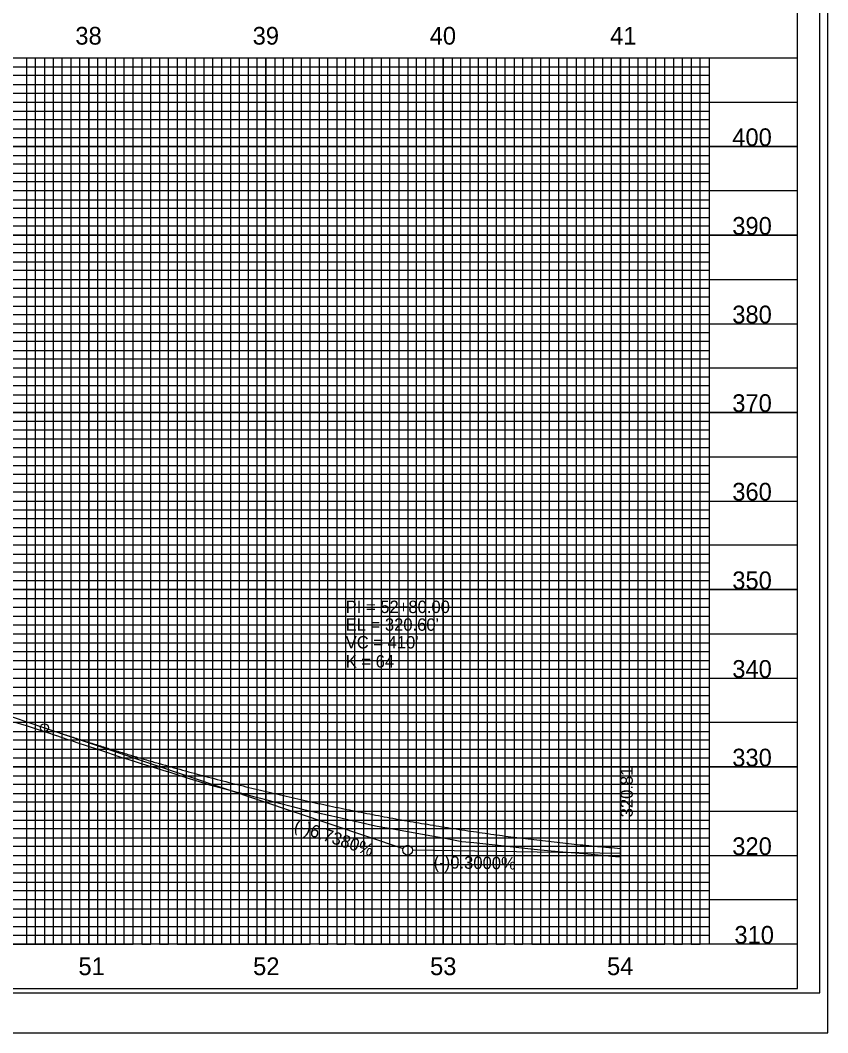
# Model space of a CAD drawing. Extents: x 571503 to 593215, y -77195 to -51828.
# Drawn here: x 583558 to 584014, y -74015 to -73444 of the extents above; entities that cross this region are included whole.
import ezdxf

# ---------------------------------------------------------------- set-up
doc = ezdxf.new("R2010")
doc.units = 0
for name, color, linetype in [('Exist Vertical Profile Ground Line', 7, 'Continuous'), ('Exist Vertical Profile Horizontal Axis Label Major', 7, 'Continuous'), ('Exist Vertical Profile Vertical Axis Label', 7, 'Continuous'), ('Prop Vertical Profile Curve Label', 7, 'Continuous'), ('Prop Vertical Profile Grade', 7, 'Continuous'), ('Prop Vertical Profile Grade Label', 7, 'Continuous'), ('Prop VPI Label', 7, 'Continuous'), ('Sheet Cutting Line CELL', 7, 'Continuous'), ('Sheet DOT Grid CELL', 7, 'Continuous'), ('Sheet Layout Profile Border Port 2', 7, 'Continuous'), ('Sheet Plot Border Inside CELL', 7, 'Continuous'), ('Sheet Plot Border Outside CELL', 7, 'Continuous'), ('Sheet Profile CELL', 7, 'Continuous'), ('Sheet Profile Grid Major CELL', 7, 'Continuous'), ('Sheet Profile Grid Middle CELL', 7, 'Continuous'), ('Sheet Profile Grid Minor CELL', 7, 'Continuous')]:
    doc.layers.add(name, color=color, linetype=linetype)

msp = doc.modelspace()

# ---------------------------------------------------------------- linework, layer by layer
at = {"layer": 'Exist Vertical Profile Ground Line'}
for points in [[(583555.87, -73840.05), (583558.44, -73840.84), (583561.62, -73841.79), (583562.84, -73842.15), (583567.37, -73843.66), (583573.12, -73845.57), (583578.65, -73847.4), (583578.87, -73847.47)], [(583578.87, -73847.47), (583584.62, -73849.4), (583587.3, -73850.29), (583590.38, -73851.31), (583596.13, -73853.22), (583601.88, -73855.13), (583607.63, -73857.04), (583610.72, -73858.07), (583613.38, -73858.96), (583615.62, -73859.71), (583619.13, -73860.81), (583624.88, -73862.62), (583630.63, -73864.43), (583632.26, -73864.94), (583636.38, -73866.19), (583640.7, -73867.49), (583642.14, -73867.94), (583647.89, -73869.75), (583653.64, -73871.56), (583659.39, -73873.37), (583663.93, -73874.8), (583665.14, -73875.16), (583668.66, -73876.22), (583670.89, -73876.81), (583676.64, -73878.31), (583680.58, -73879.33), (583682.39, -73879.8), (583688.15, -73881.28), (583690.06, -73881.77), (583693.9, -73882.77), (583699.65, -73884.26), (583705.4, -73885.76), (583711.15, -73887.26), (583712.06, -73887.5), (583716.9, -73888.74), (583717.61, -73888.92), (583719.13, -73889.27), (583722.65, -73890.06), (583728.12, -73891.3), (583728.4, -73891.37), (583734.15, -73892.68), (583739.26, -73893.84), (583739.91, -73893.99), (583745.66, -73895.29), (583751.41, -73896.59), (583757.16, -73897.9), (583759.8, -73898.5), (583762.91, -73899.06), (583766.56, -73899.72), (583768.66, -73900.1), (583785.35, -73903.1), (583799, -73905.58), (583807.46, -73907.1), (583814.21, -73907.83), (583831.48, -73909.69), (583846.42, -73911.31), (583855.79, -73912.32), (583862.22, -73912.89), (583878.67, -73914.22), (583894.28, -73915.59), (583896.98, -73915.81)]]:
    msp.add_lwpolyline(points, dxfattribs=at)
at = {"layer": 'Prop Vertical Profile Curve Label'}
msp.add_circle((583571.98, -73843.03), 2.25, dxfattribs=at)
at = {"layer": 'Prop Vertical Profile Grade'}
msp.add_line((583441.98, -73799.23), (583571.98, -73843.03), dxfattribs=at)
msp.add_spline([(583571.98, -73843.03), (583578.48, -73845.2), (583584.98, -73847.34), (583591.48, -73849.45), (583597.98, -73851.52), (583604.48, -73853.56), (583610.98, -73855.57), (583617.48, -73857.55), (583623.98, -73859.49), (583630.48, -73861.4), (583636.98, -73863.27), (583643.48, -73865.11), (583649.98, -73866.92), (583656.48, -73868.7), (583662.98, -73870.44), (583669.48, -73872.15), (583675.98, -73873.82), (583682.48, -73875.46), (583688.98, -73877.07), (583695.48, -73878.65), (583701.98, -73880.19), (583708.48, -73881.7), (583714.98, -73883.18), (583721.48, -73884.62), (583727.98, -73886.03), (583734.48, -73887.41), (583740.98, -73888.75), (583747.48, -73890.06), (583753.98, -73891.34), (583760.48, -73892.59), (583766.98, -73893.8), (583773.48, -73894.98), (583779.98, -73896.12), (583786.48, -73897.23), (583792.98, -73898.31), (583799.48, -73899.36), (583805.98, -73900.37), (583812.48, -73901.35), (583818.98, -73902.29), (583825.48, -73903.21), (583831.98, -73904.09), (583838.48, -73904.93), (583844.98, -73905.75), (583851.48, -73906.53), (583857.98, -73907.27), (583864.48, -73907.99), (583870.98, -73908.67), (583877.48, -73909.32), (583883.98, -73909.93), (583890.48, -73910.51), (583896.98, -73911.06)], degree=3, dxfattribs=at)
at = {"layer": 'Prop VPI Label'}
for p, q in [((583571.98, -73843.03), (583774.38, -73911.22)), ((583896.98, -73913.89), (583779.73, -73912.14))]:
    msp.add_line(p, q, dxfattribs=at)
msp.add_circle((583776.98, -73912.09), 2.75, dxfattribs=at)
at = {"layer": 'Sheet Cutting Line CELL'}
msp.add_line((582329.98, -74015.09), (584013.98, -74015.09), dxfattribs=at)
at = {"layer": 'Sheet DOT Grid CELL'}
for p, q in [((582496.98, -73465.09), (583996.87, -73465.09)), ((583596.98, -73465.09), (583596.98, -73965.09)), ((583646.98, -73465.09), (583646.98, -73965.09)), ((583696.98, -73465.09), (583696.98, -73965.09)), ((583746.98, -73465.09), (583746.98, -73965.09)), ((583796.98, -73465.09), (583796.98, -73965.09)), ((583846.98, -73465.09), (583846.98, -73965.09)), ((583896.98, -73465.09), (583896.98, -73965.09)), ((583946.98, -73465.09), (583946.98, -73965.09)), ((582496.98, -73515.09), (583996.87, -73515.09)), ((582496.98, -73565.09), (583996.87, -73565.09)), ((582496.98, -73615.09), (583996.87, -73615.09)), ((582496.98, -73665.09), (583996.87, -73665.09)), ((582496.98, -73715.09), (583996.87, -73715.09)), ((582496.98, -73765.09), (583996.87, -73765.09)), ((582496.98, -73815.09), (583996.87, -73815.09)), ((582496.98, -73865.09), (583996.87, -73865.09)), ((582496.98, -73915.09), (583996.87, -73915.09))]:
    msp.add_line(p, q, dxfattribs=at)
at = {"layer": 'Sheet Layout Profile Border Port 2'}
msp.add_lwpolyline([(582546.98, -73465.09), (583946.98, -73465.09), (583946.98, -73965.09), (582546.98, -73965.09)], close=True, dxfattribs=at)
at = {"layer": 'Sheet Plot Border Inside CELL'}
msp.add_lwpolyline([(582342.98, -73992.64), (584009.48, -73992.64), (584009.48, -72937.54), (582342.98, -72937.54)], close=True, dxfattribs=at)
at = {"layer": 'Sheet Plot Border Outside CELL'}
msp.add_lwpolyline([(582329.98, -74015.09), (584013.98, -74015.09), (584013.98, -72915.09), (582329.98, -72915.09)], close=True, dxfattribs=at)
at = {"layer": 'Sheet Profile CELL'}
for p, q in [((582496.98, -73465.09), (583996.98, -73465.09)), ((583996.98, -73965.09), (582496.98, -73965.09)), ((582496.98, -73990.09), (583996.98, -73990.09))]:
    msp.add_line(p, q, dxfattribs=at)
msp.add_lwpolyline([(583996.98, -72940.09), (582496.98, -72940.09), (582496.98, -73990.09), (583996.98, -73990.09)], close=True, dxfattribs=at)
at = {"layer": 'Sheet Profile Grid Major CELL'}
for p, q in [((583596.98, -73465.09), (583646.98, -73465.09)), ((583696.98, -73465.09), (583746.98, -73465.09)), ((583796.98, -73465.09), (583846.98, -73465.09)), ((583896.98, -73465.09), (583946.98, -73465.09)), ((583896.98, -73965.09), (583896.98, -73965.09))]:
    msp.add_line(p, q, dxfattribs=at)
for points in [[(583546.98, -73965.09), (583596.98, -73965.09), (583596.98, -73465.09), (583646.98, -73465.09), (583646.98, -73965.09), (583696.98, -73965.09), (583696.98, -73465.09), (583746.98, -73465.09), (583746.98, -73965.09), (583796.98, -73965.09), (583796.98, -73465.09), (583846.98, -73465.09), (583846.98, -73965.09), (583896.98, -73965.09), (583896.98, -73965.09), (583896.98, -73465.09), (583946.98, -73465.09), (583946.98, -73965.09)], [(583996.98, -73515.09), (582496.98, -73515.09)], [(583996.98, -73565.09), (582496.98, -73565.09), (582496.98, -73615.09), (583996.98, -73615.09)], [(583996.98, -73665.09), (582496.98, -73665.09), (582496.98, -73715.09), (583996.98, -73715.09)], [(583996.98, -73765.09), (582496.98, -73765.09), (582496.98, -73815.09), (583996.98, -73815.09)], [(583996.98, -73865.09), (582496.98, -73865.09), (582496.98, -73865.09), (582496.98, -73915.09), (583996.98, -73915.09)], [(583996.98, -73965.09), (582496.98, -73965.09)]]:
    msp.add_lwpolyline(points, dxfattribs=at)
at = {"layer": 'Sheet Profile Grid Middle CELL'}
for points in [[(583521.98, -73465.09), (583571.98, -73465.09), (583571.98, -73965.09), (583621.98, -73965.09), (583621.98, -73465.09), (583671.98, -73465.09), (583671.98, -73965.09), (583721.98, -73965.09), (583721.98, -73465.09), (583771.98, -73465.09), (583771.98, -73965.09), (583821.98, -73965.09), (583821.98, -73465.09), (583871.98, -73465.09), (583871.98, -73965.09), (583921.98, -73965.09), (583921.98, -73465.09)], [(582496.98, -73490.09), (583996.98, -73490.09)], [(583996.98, -73540.09), (582496.98, -73540.09), (582496.98, -73590.09), (583996.98, -73590.09)], [(583996.98, -73640.09), (582496.98, -73640.09), (582496.98, -73690.09), (583996.98, -73690.09)], [(583996.98, -73740.09), (582496.98, -73740.09), (582496.98, -73790.09), (583996.98, -73790.09)], [(583996.98, -73840.09), (582496.98, -73840.09), (582496.98, -73890.09), (583996.98, -73890.09)], [(583996.98, -73940.09), (582496.98, -73940.09)]]:
    msp.add_lwpolyline(points, dxfattribs=at)
at = {"layer": 'Sheet Profile Grid Minor CELL'}
for p, q in [((582546.98, -73470.09), (583946.98, -73470.09)), ((583946.98, -73475.09), (582546.98, -73475.09)), ((582546.98, -73480.09), (583946.98, -73480.09)), ((583946.98, -73485.09), (582546.98, -73485.09)), ((582546.98, -73495.09), (583946.98, -73495.09)), ((583946.98, -73500.09), (582546.98, -73500.09)), ((582546.98, -73505.09), (583946.98, -73505.09)), ((583946.98, -73510.09), (582546.98, -73510.09)), ((582546.98, -73520.09), (583946.98, -73520.09)), ((583946.98, -73525.09), (582546.98, -73525.09)), ((582546.98, -73530.09), (583946.98, -73530.09)), ((583946.98, -73535.09), (582546.98, -73535.09)), ((582546.98, -73545.09), (583946.98, -73545.09)), ((583946.98, -73550.09), (582546.98, -73550.09)), ((582546.98, -73555.09), (583946.98, -73555.09)), ((583946.98, -73560.09), (582546.98, -73560.09)), ((582546.98, -73570.09), (583946.98, -73570.09)), ((583946.98, -73575.09), (582546.98, -73575.09)), ((582546.98, -73580.09), (583946.98, -73580.09)), ((583946.98, -73585.09), (582546.98, -73585.09)), ((582546.98, -73595.09), (583946.98, -73595.09)), ((583946.98, -73600.09), (582546.98, -73600.09)), ((582546.98, -73605.09), (583946.98, -73605.09)), ((583946.98, -73610.09), (582546.98, -73610.09)), ((582546.98, -73620.09), (583946.98, -73620.09)), ((583946.98, -73625.09), (582546.98, -73625.09)), ((582546.98, -73630.09), (583946.98, -73630.09)), ((583946.98, -73635.09), (582546.98, -73635.09)), ((582546.98, -73645.09), (583946.98, -73645.09)), ((583946.98, -73650.09), (582546.98, -73650.09)), ((582546.98, -73655.09), (583946.98, -73655.09)), ((583946.98, -73660.09), (582546.98, -73659.94)), ((582546.98, -73670.09), (583946.98, -73670.09)), ((583946.98, -73675.09), (582546.98, -73675.09)), ((582546.98, -73680.09), (583946.98, -73680.09)), ((583946.98, -73685.09), (582546.98, -73685.09)), ((582546.98, -73695.09), (583946.98, -73695.09)), ((583946.98, -73700.09), (582546.98, -73700.09)), ((582546.98, -73705.09), (583946.98, -73705.09)), ((583946.98, -73710.09), (582546.98, -73710.09)), ((582546.98, -73720.09), (583946.98, -73720.09)), ((583946.98, -73725.09), (582546.98, -73725.09)), ((582546.98, -73730.09), (583946.98, -73730.09)), ((583946.98, -73735.09), (582546.98, -73735.09)), ((582546.98, -73745.09), (583946.98, -73745.09)), ((583946.98, -73750.09), (582546.98, -73750.09)), ((582546.98, -73755.09), (583946.98, -73755.09)), ((583946.98, -73760.09), (582546.98, -73760.09)), ((582546.98, -73770.09), (583946.98, -73770.09)), ((583946.98, -73775.09), (582546.98, -73775.09)), ((582546.98, -73780.09), (583946.98, -73780.09)), ((583946.98, -73785.09), (582546.98, -73785.09)), ((582546.98, -73795.09), (583946.98, -73795.09)), ((583946.98, -73800.09), (582546.98, -73800.09)), ((582546.98, -73805.09), (583946.98, -73805.09)), ((583946.98, -73810.09), (582546.98, -73810.09)), ((582546.98, -73820.09), (583946.98, -73820.09)), ((583946.98, -73825.09), (582546.98, -73825.09)), ((582546.98, -73830.09), (583946.98, -73830.09)), ((583946.98, -73835.09), (582546.98, -73835.09)), ((582546.98, -73845.09), (583946.98, -73845.09)), ((583946.98, -73850.09), (582546.98, -73850.09)), ((582546.98, -73855.09), (583946.98, -73855.09)), ((583946.98, -73860.09), (582546.98, -73860.09)), ((582546.98, -73870.09), (583946.98, -73870.09)), ((583946.98, -73875.09), (582546.98, -73875.09)), ((582546.98, -73880.09), (583946.98, -73880.09)), ((583946.98, -73885.09), (582546.98, -73885.09)), ((582546.98, -73895.09), (583946.98, -73895.09)), ((583946.98, -73900.09), (582546.98, -73900.09)), ((582546.98, -73905.09), (583946.98, -73905.09)), ((583946.98, -73910.09), (582546.98, -73910.09)), ((582546.98, -73920.09), (583946.98, -73920.09)), ((583946.98, -73925.09), (582546.98, -73925.09)), ((582546.98, -73930.09), (583946.98, -73930.09)), ((583946.98, -73935.09), (582546.98, -73935.09)), ((582546.98, -73945.09), (583946.98, -73945.09)), ((583946.98, -73950.09), (582546.98, -73950.09)), ((582546.98, -73955.09), (583946.98, -73955.09)), ((582546.98, -73960.09), (583946.98, -73960.09)), ((583946.98, -73960.09), (583946.98, -73960.09))]:
    msp.add_line(p, q, dxfattribs=at)
for points in [[(583556.98, -73465.09), (583561.98, -73465.09), (583561.98, -73965.09), (583566.98, -73965.09), (583566.98, -73465.09), (583576.98, -73465.09), (583576.98, -73965.09), (583581.98, -73965.09), (583581.98, -73465.09), (583586.98, -73465.09), (583586.98, -73965.09), (583591.98, -73965.09), (583591.98, -73465.09), (583601.98, -73465.09), (583601.98, -73965.09), (583606.98, -73965.09), (583606.98, -73465.09), (583611.98, -73465.09), (583611.98, -73965.09), (583616.98, -73965.09), (583616.98, -73465.09), (583626.98, -73465.09), (583626.98, -73965.09), (583631.98, -73965.09), (583631.98, -73465.09), (583636.98, -73465.09), (583636.98, -73965.09), (583641.98, -73965.09), (583641.98, -73465.09), (583651.98, -73465.09), (583651.98, -73965.09), (583656.98, -73965.09), (583656.98, -73465.09), (583661.98, -73465.09), (583661.98, -73965.09), (583666.98, -73965.09), (583666.98, -73465.09), (583676.98, -73465.09), (583676.98, -73965.09), (583681.98, -73965.09), (583681.98, -73465.09), (583686.98, -73465.09), (583686.98, -73965.09)], [(583686.98, -73965.09), (583691.98, -73965.09), (583691.98, -73465.09), (583701.98, -73465.09), (583701.98, -73965.09), (583706.98, -73965.09), (583706.98, -73465.09), (583711.98, -73465.09), (583711.98, -73965.09), (583716.98, -73965.09), (583716.98, -73465.09), (583726.98, -73465.09), (583726.98, -73965.09), (583731.98, -73965.09), (583731.98, -73465.09), (583736.98, -73465.09), (583736.98, -73965.09), (583741.98, -73965.09), (583741.98, -73465.09), (583751.98, -73465.09), (583751.98, -73965.09), (583756.98, -73965.09), (583756.98, -73465.09), (583761.98, -73465.09), (583761.98, -73965.09), (583766.98, -73965.09), (583766.98, -73465.09), (583776.98, -73465.09), (583776.98, -73965.09), (583781.98, -73965.09), (583781.98, -73465.09), (583786.98, -73465.09), (583786.98, -73965.09), (583791.98, -73965.09), (583791.98, -73465.09), (583801.98, -73465.09), (583801.98, -73965.09), (583806.98, -73965.09), (583806.98, -73465.09), (583811.98, -73465.09), (583811.98, -73965.09), (583816.98, -73965.09), (583816.98, -73465.09), (583826.98, -73465.09), (583826.98, -73965.09), (583831.98, -73965.09), (583831.98, -73465.09), (583836.98, -73465.09), (583836.98, -73965.09), (583841.98, -73965.09), (583841.98, -73465.09), (583851.98, -73465.09), (583851.98, -73965.09), (583856.98, -73965.09), (583856.98, -73465.09), (583861.98, -73465.09), (583861.98, -73965.09), (583866.98, -73965.09), (583866.98, -73465.09), (583876.98, -73465.09), (583876.98, -73965.09), (583881.98, -73965.09), (583881.98, -73465.09), (583886.98, -73465.09), (583886.98, -73965.09), (583891.98, -73965.09), (583891.98, -73465.09), (583901.98, -73465.09), (583901.98, -73965.09), (583906.98, -73965.09), (583906.98, -73465.09), (583911.98, -73465.09), (583911.98, -73965.09), (583916.98, -73965.09), (583916.98, -73465.09), (583926.98, -73465.09), (583926.98, -73965.09), (583931.98, -73965.09), (583931.98, -73465.09), (583936.98, -73465.09), (583936.98, -73965.09), (583941.98, -73965.09), (583941.98, -73465.09), (583946.98, -73465.09)]]:
    msp.add_lwpolyline(points, dxfattribs=at)

# ---------------------------------------------------------------- texts
at = {"layer": 'Exist Vertical Profile Horizontal Axis Label Major'}
for s, p in [('38', (583589.45, -73457.59)), ('39', (583689.49, -73457.59)), ('40', (583789.37, -73457.59)), ('41', (583891.21, -73457.59)), ('51', (583591.21, -73982.59)), ('52', (583689.76, -73982.59)), ('53', (583789.59, -73982.59)), ('54', (583889.44, -73982.59))]:
    msp.add_text(s, height=10, dxfattribs=at).set_placement(p)
at = {"layer": 'Exist Vertical Profile Vertical Axis Label'}
for s, p in [('400', (583960.11, -73514.84)), ('390', (583960.11, -73564.84)), ('380', (583960.11, -73614.84)), ('370', (583960.11, -73664.84)), ('360', (583960.11, -73714.84)), ('350', (583960.11, -73764.84)), ('340', (583960.11, -73814.84)), ('330', (583960.11, -73864.84)), ('320', (583960.11, -73914.84)), ('310', (583961.31, -73964.84))]:
    msp.add_text(s, height=10, dxfattribs=at).set_placement(p)
at = {"layer": 'Prop Vertical Profile Curve Label'}
for s, p in [("VC = 410'", (583741.98, -73798.29)), ('K = 64', (583741.98, -73809.04))]:
    msp.add_text(s, height=7, dxfattribs=at).set_placement(p)
at = {"layer": 'Prop Vertical Profile Grade Label'}
for s, rotation, p in [('(-)6.7380%', 341.3813, (583712.33, -73900.87)), ('(-)0.3000%', 359.1406, (583791.59, -73922.31))]:
    msp.add_text(s, height=7, rotation=rotation, dxfattribs=at).set_placement(p)
at = {"layer": 'Prop VPI Label'}
for s, p in [('PI = 52+80.00', (583741.98, -73778.29)), ("EL = 320.60'", (583741.98, -73788.29))]:
    msp.add_text(s, height=7, dxfattribs=at).set_placement(p)
msp.add_text('320.81', height=7, rotation=90, dxfattribs=at).set_placement((583903.98, -73893.56))

doc.saveas('drawing.dxf')
